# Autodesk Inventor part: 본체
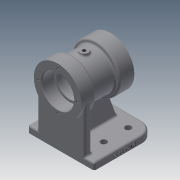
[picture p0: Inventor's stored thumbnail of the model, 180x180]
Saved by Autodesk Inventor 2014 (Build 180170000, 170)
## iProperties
Created: 2020-06
Part Number: 본체
Material: Generic
Document SubType Name: Modeling
Designer: kh
Density: 1 g/cm^3
Appearance: Default
Author: kh
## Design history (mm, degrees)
sketch "Sketch1"
  geometry: L1 (-45, -49)-(45, -49); L2 (45, -49)-(45, 49); L3 (45, 49)-(-45, 49); L4 (-45, 49)-(-45, -49); L5 (-45, -49)-(45, 49); L6 (45, -49)-(-45, 49); 1 further point
  constraints: 12 end point, 2 midpoint, 2 parallel, 1 horizontal, 1 perpendicular
  dimensions: "d0" = 90 distance of L2.end L3.end; "d1" = 98 distance of L1.end L2.end
extrude "Extrusion1" new body sketch "Sketch1" distance "d2" = 10; taper "d3" = 0 deg
fillet "Fillet2" dims "d15" = 20
sketch "Sketch3"
  geometry: A1 r 20 centre (-25, 29) between (-25, 49) and (-45, 29) reference; A2 r 20 centre (-25, -29) between (-45, -29) and (-25, -49) reference; 1 further point
hole "Hole2" sketch "Sketch3" at (-25, -29), (-25, 29) diameter "d16" = 9; stored, may be unused: countersink angle "d20" = 90 deg, drill point angle "d22" = 118 deg; dims "d17" = 6, "d18" = 4, "d19" = 2, "d21" = 8
pattern_linear "Rectangular Pattern2" dims "d25" = 36
sketch "Sketch4"
  geometry: L1 (-45, 10)-(45, 10) reference; L2 (45, 10)-(45, 0) reference; L3 (45, 0)-(-45, 0) reference; L4 (-45, 0)-(-45, 10) reference; L5 (28, 115)-(6, 115); L6 (-50, 115)-(-50, 80); L7 (-50, 80)-(28, 80); L8 (28, 80)-(28, 115); L9 (6, 115)-(6, 109); L10 (6, 109)-(-28, 109); L11 (-28, 109)-(-28, 115); L12 (-28, 115)-(-50, 115); L13 (6, 115)-(-28, 115); 1 further point
  constraints: 18 end point, 7 perpendicular, 5 parallel, 3 horizontal, 1 collinear
  dimensions: "d26" = 35 distance of L6.start L6.end; "d27" = 5 distance between parallel lines of L4 L6; "d28" = 78 distance of L5.start L6.start; "d29" = 80 distance between parallel lines of L3 L7; "d30" = 22 distance of L5.start L5.end; "d31" = 29 distance between parallel lines of L7 L10
revolve "Revolution1" sketch "Sketch4" stored, may be unused: angle "d32" = 90 deg
sketch "Sketch5"
  geometry: L1 (-10, 0)-(-10, 98) reference; L2 (-10, 98)-(0, 98) reference; L3 (0, 98)-(0, 0) reference; L4 (0, 0)-(-10, 0) reference; L5 (-10, 0)-(-10, 98) reference; L6 (-80, 14)-(-10, 14); L7 (-80, 84)-(-10, 84); A1 r 35 centre (-80, 49) between (-80, 14) and (-80, 84) reference; 1 further point
  constraints: 4 end point, 2 perpendicular, 2 point on circle, 2 point on line, 2 tangent
extrude "Extrusion2" join sketch "Sketch5" distance "d33" = 10; taper "d34" = 0 deg
sketch "Sketch6"
  geometry: L1 (28, 115)-(28, 45) reference; L2 (28, 45)-(6, 45) reference; L3 (6, 45)-(6, 51) reference; L4 (6, 51)-(-28, 51) reference; L5 (-28, 51)-(-28, 45) reference; L6 (-28, 45)-(-35, 45) reference; L7 (-35, 45)-(-35, 10) reference; L8 (-35, 10)-(45, 10) reference; L9 (45, 10)-(45, 0) reference; L10 (45, 0)-(-45, 0) reference; L11 (-45, 0)-(-45, 45) reference; L12 (-45, 45)-(-50, 45) reference; L13 (-50, 45)-(-50, 115) reference; L14 (-50, 115)-(-28, 115) reference; L15 (-28, 115)-(-28, 109) reference; L16 (-28, 109)-(6, 109) reference; L17 (6, 109)-(6, 115) reference; L18 (6, 115)-(28, 115) reference; L19 (20.261, 45)-(33, 10); 1 further point
  constraints: 2 end point, 2 point on line
  dimensions: "d35" = 12 distance from line of L9 L19.end; "d36" = 70 deg angle of L8 L19
feature "Rib1" sketch "Sketch6" dims "d37" = 1, "d38" = 10, "d39" = 0, "d40" = 0, "d41" = 1, "d42" = 1
sketch "Sketch7"
  geometry: L1 (28, 115)-(28, 45) reference; L2 (28, 45)-(20.261, 45) reference; L3 (20.261, 45)-(33, 10) reference; L4 (33, 10)-(45, 10) reference; L5 (45, 10)-(45, 0) reference; L6 (45, 0)-(-45, 0) reference; L7 (-45, 0)-(-45, 45) reference; L8 (-45, 45)-(-50, 45) reference; L9 (-50, 45)-(-50, 115) reference; L10 (-50, 115)-(-28, 115) reference; L11 (-28, 115)-(-28, 109) reference; L12 (-28, 109)-(6, 109) reference; L13 (6, 109)-(6, 115) reference; L14 (6, 115)-(28, 115) reference; L15 (-28, 109)-(6, 109) reference; L16 (-11, 109)-(-5, 109); L17 (-5, 109)-(-5, 99.595); L18 (-5, 99.595)-(-11, 99.595); L19 (-11, 99.595)-(-11, 109); L20 (-11, 109)-(-5, 109); L21 (-5, 109)-(-5, 112); L22 (-5, 112)-(-11, 112); L23 (-11, 112)-(-11, 109); 1 further point
  constraints: 16 end point, 4 parallel, 2 horizontal, 2 perpendicular, 1 collinear, 1 midpoint
  dimensions: "d43" = 6 distance of L21.end L22.end; "d44" = 3 distance between parallel lines of L22 L12
revolve "Revolution2" sketch "Sketch7" stored, may be unused: angle "d45" = 90 deg
sketch "Sketch8"
  geometry: L1 (28, 115)-(28, 45) reference; L2 (28, 45)-(20.261, 45) reference; L3 (20.261, 45)-(33, 10) reference; L4 (33, 10)-(45, 10) reference; L5 (45, 10)-(45, 0) reference; L6 (45, 0)-(-45, 0) reference; L7 (-45, 0)-(-45, 45) reference; L8 (-45, 45)-(-50, 45) reference; L9 (-50, 45)-(-50, 115) reference; L10 (-50, 115)-(-28, 115) reference; L11 (-28, 115)-(-28, 109) reference; L12 (-28, 109)-(-17, 109) reference; L13 (-17, 109)-(-17, 112) reference; L14 (-17, 112)-(-5, 112) reference; L15 (-5, 112)-(-5, 109) reference; L16 (-5, 109)-(6, 109) reference; L17 (6, 109)-(6, 115) reference; L18 (6, 115)-(28, 115) reference; L19 (28, 45)-(28, 115) reference; L20 (28, 80)-(10, 80); L21 (10, 80)-(10, 103.2); L22 (10.3, 103.5)-(28, 103.5); L23 (28, 103.5)-(28, 80); L24 (10, 80)-(4, 80); L25 (4, 80)-(4, 100); L26 (4, 100)-(10, 100); L27 (10, 100)-(10, 80); L28 (4, 80)-(-26, 80); L29 (-26, 80)-(-26, 103); L30 (-26, 103)-(4, 103); L31 (4, 103)-(4, 80); L32 (-26, 80)-(-32, 80); L33 (-32, 80)-(-32, 100); L34 (-32, 100)-(-26, 100); L35 (-26, 100)-(-26, 80); L36 (-50, 45)-(-50, 115) reference; L37 (-32, 80)-(-50, 80); L38 (-50, 80)-(-50, 103.5); L39 (-50, 103.5)-(-32.3, 103.5); L40 (-32, 103.2)-(-32, 80); A1 r 0.3 centre (10.3, 103.2) between (10.3, 103.5) and (10, 103.2); A2 r 0.3 centre (-32.3, 103.2) between (-32, 103.2) and (-32.3, 103.5); 2 further points
  constraints: 40 end point, 10 parallel, 5 horizontal, 5 perpendicular, 4 collinear, 4 point on circle, 4 tangent, 3 point on line, 2 centre point, 1 equal radius, 1 midpoint
  dimensions: "d46" = 18 distance of L38.end point (-32, 103.5); "d47" = 30 distance of L29.end L30.end; "d48" = 20 distance between parallel lines of L32 L34; "d49" = 23.5 distance between parallel lines of L37 L39; "d50" = 23 distance between parallel lines of L28 L30; "d51" = 0.3 radius of A1
revolve "Revolution3" sketch "Sketch8" stored, may be unused: angle "d52" = 90 deg
chamfer "Chamfer1" distance "d53" = 1; stored, may be unused: second distance "d54" = 2, angle "d55" = 45 deg
fillet "Fillet3" dims "d56" = 3
sketch "Sketch9"
  geometry: C1 r 35 at (0, 0) reference; 2 further points
  constraints: 1 horizontal alignment
  dimensions: "d57" = 28.5 distance of C1.centre point (-28.5, 0)
hole "Hole3" sketch "Sketch9" at (-28.5, 0) diameter "d58" = 3.242; stored, may be unused: countersink angle "d62" = 90 deg, drill point angle "d64" = 118 deg; dims "d59" = 10, "d60" = 4, "d61" = 2, "d63" = 12
pattern_circular "Circular Pattern1" dims angle "d66" = 360 deg
workplane "Work Plane1"
mirror "Mirror1"
hole "Hole4" diameter "d70" = 5.188; stored, may be unused: countersink angle "d74" = 90 deg, drill point angle "d76" = 118 deg; dims "d68" = 10, "d69" = 10, "d71" = 10, "d72" = 4, "d73" = 2, "d75" = 21
fillet "Fillet4" dims "d77" = 3
fillet "Fillet5" dims "d78" = 3
fillet "Fillet6" dims "d79" = 3
sketch "Sketch10"
  geometry: L1 (67, 0)-(0, 0) reference; L2 (70, -7)-(70, 0) reference; 2 further points
  constraints: 1 other
  dimensions: "d80" = 4 distance from line of L1 point (25, -4); "d81" = 45 distance from line of point (25, -4) L2
emboss "Emboss1" sketch "Sketch10" dims "d0" = 90, "d1" = 98, "d82" = 0.5, "d83" = 0
body "Solid1"
node "Project Cut Edges1"
node "Project Cut Edges2"
node "Project Cut Edges3"
node "Project Cut Edges4"
node "Project Cut Edges5"
